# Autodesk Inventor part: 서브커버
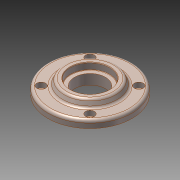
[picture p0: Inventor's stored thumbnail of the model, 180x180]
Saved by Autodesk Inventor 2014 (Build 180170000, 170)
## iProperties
Created: 2013-01
Part Number: 서브커버
Document SubType Name: Modeling
Designer: 한국산업디자인학원[gmhk.co.kr]
Density: 7.25 g/cm^3
Material: 주철
Mass: 439.929 g
Surface Area: 178.476 cm^2
Volume: 60.6798 cm^3
Appearance: 강철(1)
Author: 한국산업디자인학원[gmhk.co.kr]
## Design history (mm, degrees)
sketch "스케치2"
  geometry: L1 (-45, 0)-(0, 0); L2 (-25.784, -7)-(25.784, -7) reference; L3 (0, -7)-(0, 15); L4 (-31, -23)-(-31, 0) reference; L5 (-26.5, -7)-(-26.5, -3); L6 (-26.5, -3)-(0, -3); L7 (-26.5, -7)-(-31, -7); L8 (-31, 0)-(-45, 0); L9 (-45, 0)-(-45, 8); L10 (-45, 8)-(-30, 8); L11 (-30, 8)-(-26.736, 15); L12 (-26.736, 15)-(0, 15)
  constraints: 25 end point, 6 perpendicular, 3 point on line, 1 collinear, 1 horizontal, 1 midpoint, 1 parallel, 1 vertical, 3 other
  dimensions: "d0" = 53 diameter of L5 L3; "d1" = 4 distance between parallel lines of L6 L2; "d2" = 8 distance between parallel lines of L10 L1; "d3" = 7 distance between parallel lines of L12 L10; "d4" = 60 diameter of L10.end L3; "d5" = 115 deg angle of L11 L10; "d27" = 90 diameter of L9 L3
revolve "회전1" sketch "스케치2" stored, may be unused: angle "d6" = 90 deg
hole "구멍1" diameter "d9" = 33; stored, may be unused: countersink angle "d13" = 90 deg, drill point angle "d15" = 118 deg; dims "d10" = 6, "d11" = 42, "d12" = 7.3, "d14" = 8, "d38" = 10, "d39" = 10
fillet "모깎기1" dims "d16" = 3
chamfer "모따기1" distance "d17" = 0.7; stored, may be unused: second distance "d18" = 2, angle "d19" = 30 deg
sketch "스케치3"
  geometry: C1 r 2.067 at (26.163, 26.163) reference; 1 further point
hole "구멍2" sketch "스케치3" at (26.163, 26.163) diameter "d20" = 5.4; stored, may be unused: countersink angle "d24" = 90 deg, drill point angle "d26" = 118 deg; dims "d21" = 6, "d22" = 9.5, "d23" = 5.5, "d25" = 8
fillet "모깎기2" dims "d31" = 0.3
fillet "모깎기3" dims "d32" = 3
chamfer "모따기2" distance "d35" = 1; stored, may be unused: second distance "d36" = 2, angle "d37" = 45 deg
node "솔리드1"
pattern_circular "원형 패턴1" dims angle "d29" = 360 deg
node "참조3"
